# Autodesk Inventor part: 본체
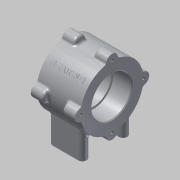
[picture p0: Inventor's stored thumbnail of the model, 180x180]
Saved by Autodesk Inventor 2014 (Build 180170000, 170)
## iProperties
Created: 2015-03
Part Number: 본체
Material: 알루미늄 6061
Document SubType Name: Modeling
Designer: Administrator
Mass: 450.776 g
Surface Area: 332.745 cm^2
Volume: 166.338 cm^3
Density: 2.71 g/cm^3
Appearance: 알루미늄 - 평지
Author: Administrator
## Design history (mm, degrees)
sketch "스케치2"
  geometry: C1 r 37 at (0, 56); 1 further point
  constraints: 1 centre point, 1 vertical alignment
  dimensions: "d0" = 74 diameter of C1; "d1" = 56 distance of C1.centre point (0, 0)
extrude "돌출1" new body sketch "스케치2" stored distance "d2" = 52; taper "d3" = 0 deg
sketch "스케치3"
  geometry: C1 r 7 at (0, 37); 2 further points
  constraints: 2 vertical alignment, 1 centre point, 1 other
  dimensions: "d4" = 14 diameter of C1
extrude "돌출2" join sketch "스케치3" distance "d5" = 15; taper "d6" = 0 deg
fillet "모깎기1" dims "d7" = 3
fillet "모깎기2" dims "d8" = 3
hole "구멍1" diameter "d11" = 3.242; stored, may be unused: countersink angle "d15" = 90 deg, drill point angle "d17" = 118 deg; dims "d9" = 10, "d10" = 10, "d12" = 8, "d13" = 4, "d14" = 2, "d16" = 11
sketch "스케치5"
  geometry: L1 (-15, 24)-(15, 24); L2 (-15, 19)-(15, 19); L3 (15, 29)-(-15, 29); L4 (-15, -24)-(15, -24); L5 (-15, -29)-(15, -29); L6 (15, -19)-(-15, -19); A1 r 5 centre (-15, 24) between (-15, 29) and (-15, 19); A2 r 5 centre (15, 24) between (15, 19) and (15, 29); A3 r 5 centre (-15, -24) between (-15, -19) and (-15, -29); A4 r 5 centre (15, -24) between (15, -29) and (15, -19); 3 further points
  constraints: 16 end point, 8 point on circle, 8 tangent, 4 centre point, 3 parallel, 2 midpoint, 2 vertical alignment, 1 horizontal
  dimensions: "d21" = 10 distance between parallel lines of L2 L3; "d22" = 10 distance between parallel lines of L5 L6; "d23" = 40 dimension on A2 A1; "d24" = 40 dimension on A4 A3; "d25" = 48 distance of point (0, -24) point (0, 24); "d26" = 24 distance of point (0, 24) point (0, 0)
extrude "돌출3" join sketch "스케치5" stored distance "d27" = 15; taper "d28" = 0 deg
sketch "스케치6"
  geometry: L1 (15, 19)-(-15, 19) reference; L2 (-15, 29)-(15, 29) reference; A1 r 5 centre (15, -24) between (15, -29) and (15, -19) reference; A2 r 5 centre (-15, -24) between (-15, -19) and (-15, -29) reference; A3 r 5 centre (15, 24) between (15, 19) and (15, 29) reference; A4 r 5 centre (-15, 24) between (-15, 29) and (-15, 19) reference; 5 further points
  constraints: 4 coincident
hole "구멍2" sketch "스케치6" at (-15, 24), (15, 24), (15, -24), (-15, -24) diameter "d29" = 4.134; stored, may be unused: countersink angle "d33" = 90 deg, drill point angle "d35" = 118 deg; dims "d30" = 6, "d31" = 4, "d32" = 2, "d34" = 8
fillet "모깎기3" dims "d36" = 3
hole "구멍3" diameter "d39" = 42; stored, may be unused: countersink angle "d43" = 90 deg, drill point angle "d45" = 0 deg; dims "d37" = 10, "d38" = 10, "d40" = 6, "d41" = 47, "d42" = 22, "d44" = 30
hole "구멍4" diameter "d48" = 47; stored, may be unused: countersink angle "d52" = 90 deg, drill point angle "d54" = 0 deg; dims "d46" = 10, "d47" = 10, "d49" = 6, "d50" = 47, "d51" = 22, "d53" = 22
chamfer "모따기1" distance "d55" = 1; stored, may be unused: second distance "d56" = 2, angle "d57" = 45 deg
fillet "모깎기4" dims "d58" = 0.3
sketch "스케치7"
  geometry: L1 (0, 56)-(-21, 56); L2 (0, 56)-(-26.163, 82.163); A1 r 37 centre (0, 56) between (-9.104, 91.863) and (-35.862, 65.104) reference; 2 further points
  constraints: 4 end point, 1 coincident, 1 horizontal, 1 horizontal alignment, 1 point on circle, 1 other
  dimensions: "d59" = 45 deg angle of L2 L1
node "작업 평면3"
sketch "스케치9"
  geometry: L1 (-26, 18.921)-(-26, -18.921) reference; L2 (26, -18.921)-(26, 18.921) reference; 3 further points
  constraints: 1 horizontal alignment, 1 midpoint, 1 other
  dimensions: "d61" = 26 distance from line of L1 point (0, 0)
feature "엠보싱1" sketch "스케치9" dims "d62" = 0.5, "d63" = 0
node "솔리드1"
pattern_circular "원형 패턴1" dims "d19" = 360 deg
mirror "대칭1"
node "투영된 루프1"
